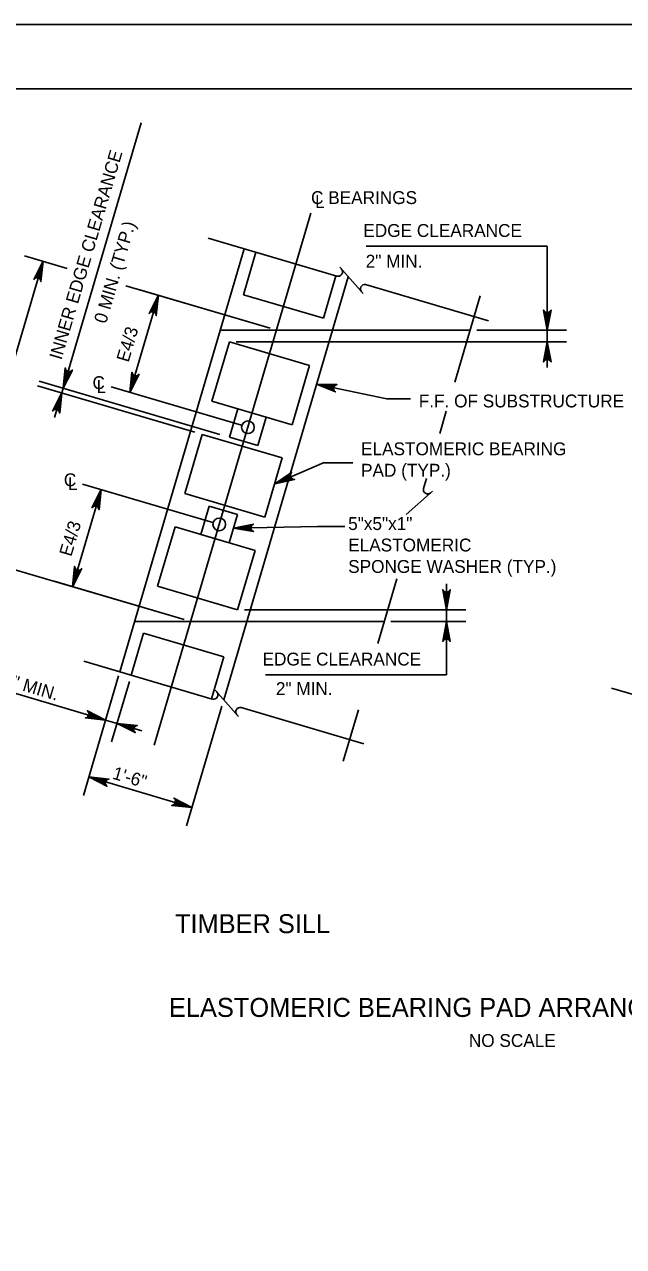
# Model space of a CAD drawing. Extents: x 638268 to 640277, y 295465 to 298435.
# Drawn here: x 639790.3 to 639930.1, y 298150.4 to 298435.5 of the extents above; entities that cross this region are included whole.
import ezdxf

# ---------------------------------------------------------------- set-up
doc = ezdxf.new("R2010")
doc.units = 0
for name, color, linetype in [('2', 7, 'Continuous'), ('3', 7, 'Continuous'), ('4', 7, 'Continuous'), ('7', 7, 'Continuous'), ('PLT-BNDY', 7, 'Continuous')]:
    doc.layers.add(name, color=color, linetype=linetype)

msp = doc.modelspace()

# ---------------------------------------------------------------- linework, layer by layer
at = {"layer": '2'}
msp.add_line((639316.46, 298420.46), (640102.46, 298420.46), dxfattribs=at)
at = {"layer": '3'}
for p, q in [((639833.22, 298385.58), (639863.23, 298376.74)), ((639812.58, 298284.45), (639841.64, 298383.1)), ((639774.66, 298312.22), (639794.68, 298380.2)), ((639800.32, 298378.54), (639790.36, 298381.47)), ((639863.93, 298378.81), (639869.34, 298372.67)), ((639847.64, 298364.6), (639814.01, 298374.5)), ((639865.89, 298376.59), (639836.83, 298277.94)), ((639869.94, 298374.77), (639898.62, 298366.32)), ((639841.42, 298372.42), (639860.11, 298366.91)), ((639896.68, 298372.12), (639890.74, 298351.98)), ((639836.06, 298364.16), (639894.33, 298364.16)), ((639838.17, 298361.4), (639856.86, 298355.9)), ((639835.93, 298339.83), (639793.74, 298352.26)), ((639830.12, 298340.34), (639793.42, 298351.16)), ((639834.09, 298347.56), (639852.79, 298342.05)), ((639840.14, 298345.77), (639846.74, 298343.83)), ((639888.77, 298345.26), (639887.23, 298340.03)), ((639831.82, 298339.84), (639850.51, 298334.34)), ((639838.19, 298339.17), (639844.8, 298337.22)), ((639884.13, 298329.51), (639883.46, 298327.24)), ((639827.74, 298326), (639846.44, 298320.49)), ((639885.52, 298326.55), (639879.39, 298321.13)), ((639833.46, 298323.12), (639840.07, 298321.17)), ((639825.47, 298318.29), (639844.17, 298312.78)), ((639831.51, 298316.51), (639838.12, 298314.56)), ((639827.62, 298296.62), (639770.34, 298313.49)), ((639877.23, 298306.11), (639872.8, 298291.07)), ((639821.39, 298304.44), (639840.09, 298298.93)), ((639816.04, 298296.18), (639874.31, 298296.18)), ((639818.15, 298293.42), (639836.84, 298287.92)), ((639804.17, 298286.93), (639834.18, 298278.09)), ((639834.87, 298280.16), (639840.28, 298274.02)), ((639840.89, 298276.12), (639869.56, 298267.67)), ((639868.25, 298275.6), (639864.71, 298263.61))]:
    msp.add_line(p, q, dxfattribs=at)
msp.add_lwpolyline([(639793.35, 298377.46), (639794.31, 298377.18), (639794.68, 298380.2)], close=True, dxfattribs=at)
for centre, start, end in [((639863.52, 298377.72), 253.588, 43.588), ((639869.75, 298373.76), 78.9166, 221.4552), ((639884.44, 298326.95), 163.588, 313.588), ((639834.47, 298279.08), 253.588, 43.588), ((639840.69, 298275.11), 78.9166, 221.4552)]:
    msp.add_arc(centre, 1.02, start, end, dxfattribs=at)
at = {"layer": '4'}
for p, q in [((639800.22, 298353.48), (639817.59, 298412.47)), ((639820.63, 298267.37), (639857.18, 298391.45)), ((639870.07, 298383.7), (639912.34, 298383.7)), ((639912.34, 298367.16), (639912.34, 298383.7)), ((639814.91, 298349.61), (639821.59, 298372.27)), ((639847.64, 298364.6), (639817.27, 298373.54)), ((639895.89, 298364.16), (639916.84, 298364.16)), ((639912.34, 298361.4), (639912.34, 298364.16)), ((639839.73, 298361.4), (639916.84, 298361.4)), ((639912.34, 298358.4), (639912.34, 298355.4)), ((639799.04, 298349.5), (639799.37, 298350.6)), ((639840.97, 298341.94), (639810.6, 298350.89)), ((639798.2, 298346.62), (639797.35, 298343.74)), ((639874.89, 298348.09), (639880.42, 298348.09)), ((639860.08, 298333.18), (639866.93, 298333.18)), ((639801.56, 298304.3), (639808.24, 298326.95)), ((639834.29, 298319.28), (639803.92, 298328.22)), ((639858.72, 298318.32), (639865.09, 298318.32)), ((639827.62, 298296.62), (639797.25, 298305.57)), ((639888.81, 298301.93), (639888.81, 298304.93)), ((639841.65, 298298.93), (639893.31, 298298.93)), ((639888.81, 298298.93), (639888.81, 298296.18)), ((639875.87, 298296.18), (639893.31, 298296.18)), ((639888.81, 298293.18), (639888.81, 298283.71)), ((639812.31, 298283.53), (639804.08, 298255.59)), ((639812.14, 298282.96), (639808, 298268.88)), ((639846.55, 298283.71), (639888.81, 298283.71)), ((639809.27, 298273.2), (639782.13, 298281.19)), ((639814.83, 298282.16), (639810.69, 298268.09)), ((639952.69, 298273.2), (639927.34, 298280.66)), ((639836.39, 298276.44), (639828.16, 298248.5)), ((639811.96, 298272.4), (639809.27, 298273.2)), ((639811.96, 298272.4), (639817.71, 298270.71)), ((639829.43, 298252.81), (639805.35, 298259.91))]:
    msp.add_line(p, q, dxfattribs=at)
for points in [[(639794.68, 298380.2), (639794.2, 298375.48), (639794.06, 298375.9), (639793.82, 298376.16), (639793.53, 298376.3), (639793.22, 298376.34), (639792.86, 298376.25), (639792.53, 298375.98), (639794.68, 298380.2), (639792.86, 298376.25), (639793.22, 298376.34), (639794.68, 298380.2), (639793.53, 298376.3), (639793.82, 298376.16), (639794.68, 298380.2), (639794.06, 298375.9)], [(639821.59, 298372.27), (639821.11, 298367.56), (639820.97, 298367.97), (639820.73, 298368.24), (639820.44, 298368.37), (639820.13, 298368.41), (639819.77, 298368.32), (639819.43, 298368.05), (639821.59, 298372.27), (639819.77, 298368.32), (639820.13, 298368.41), (639821.59, 298372.27), (639820.44, 298368.37), (639820.73, 298368.24), (639821.59, 298372.27), (639820.97, 298367.97)], [(639912.34, 298364.16), (639911.46, 298368.82), (639911.71, 298368.46), (639912.02, 298368.27), (639912.34, 298368.22), (639912.65, 298368.27), (639912.96, 298368.46), (639913.21, 298368.82), (639912.34, 298364.16), (639912.96, 298368.46), (639912.65, 298368.27), (639912.34, 298364.16), (639912.34, 298368.22), (639912.02, 298368.27), (639912.34, 298364.16), (639911.71, 298368.46)], [(639912.34, 298361.4), (639913.21, 298356.74), (639912.96, 298357.1), (639912.65, 298357.29), (639912.34, 298357.34), (639912.02, 298357.29), (639911.71, 298357.1), (639911.46, 298356.74), (639912.34, 298361.4), (639911.71, 298357.1), (639912.02, 298357.29), (639912.34, 298361.4), (639912.34, 298357.34), (639912.65, 298357.29), (639912.34, 298361.4), (639912.96, 298357.1)], [(639799.37, 298350.6), (639799.85, 298355.32), (639799.99, 298354.9), (639800.23, 298354.64), (639800.52, 298354.5), (639800.83, 298354.46), (639801.18, 298354.55), (639801.53, 298354.82), (639799.37, 298350.6), (639801.18, 298354.55), (639800.83, 298354.46), (639799.37, 298350.6), (639800.52, 298354.5), (639800.23, 298354.64), (639799.37, 298350.6), (639799.99, 298354.9)], [(639814.91, 298349.61), (639815.39, 298354.33), (639815.53, 298353.92), (639815.78, 298353.65), (639816.06, 298353.51), (639816.38, 298353.47), (639816.73, 298353.56), (639817.07, 298353.84), (639814.91, 298349.61), (639816.73, 298353.56), (639816.38, 298353.47), (639814.91, 298349.61), (639816.06, 298353.51), (639815.78, 298353.65), (639814.91, 298349.61), (639815.53, 298353.92)], [(639858.51, 298351.54), (639874.89, 298348.09)], [(639858.51, 298351.54), (639863.25, 298351.44), (639862.84, 298351.27), (639862.6, 298351), (639862.48, 298350.7), (639862.47, 298350.39), (639862.59, 298350.04), (639862.89, 298349.73), (639858.51, 298351.54), (639862.59, 298350.04), (639862.47, 298350.39), (639858.51, 298351.54), (639862.48, 298350.7), (639862.6, 298351), (639858.51, 298351.54), (639862.84, 298351.27)], [(639799.04, 298349.5), (639798.56, 298344.78), (639798.43, 298345.2), (639798.18, 298345.46), (639797.9, 298345.6), (639797.58, 298345.64), (639797.23, 298345.55), (639796.89, 298345.27), (639799.04, 298349.5), (639797.23, 298345.55), (639797.58, 298345.64), (639799.04, 298349.5), (639797.9, 298345.6), (639798.18, 298345.46), (639799.04, 298349.5), (639798.43, 298345.2)], [(639848.73, 298328.28), (639860.24, 298333.25)], [(639848.73, 298328.28), (639852.67, 298330.93), (639852.44, 298330.56), (639852.39, 298330.2), (639852.46, 298329.9), (639852.64, 298329.63), (639852.93, 298329.42), (639853.36, 298329.33), (639848.73, 298328.28), (639852.93, 298329.42), (639852.64, 298329.63), (639848.73, 298328.28), (639852.46, 298329.9), (639852.39, 298330.2), (639848.73, 298328.28), (639852.44, 298330.56)], [(639808.24, 298326.95), (639807.76, 298322.24), (639807.62, 298322.65), (639807.38, 298322.92), (639807.09, 298323.06), (639806.78, 298323.09), (639806.43, 298323), (639806.09, 298322.73), (639808.24, 298326.95), (639806.43, 298323), (639806.78, 298323.09), (639808.24, 298326.95), (639807.09, 298323.06), (639807.38, 298322.92), (639808.24, 298326.95), (639807.62, 298322.65)], [(639839.11, 298317.92), (639843.75, 298318.89), (639843.4, 298318.63), (639843.22, 298318.32), (639843.18, 298318), (639843.23, 298317.69), (639843.43, 298317.38), (639843.79, 298317.14), (639839.11, 298317.92), (639843.43, 298317.38), (639843.23, 298317.69), (639839.11, 298317.92), (639843.18, 298318), (639843.22, 298318.32), (639839.11, 298317.92), (639843.4, 298318.63)], [(639839.11, 298317.92), (639858.72, 298318.32)], [(639801.56, 298304.3), (639802.04, 298309.01), (639802.18, 298308.6), (639802.43, 298308.33), (639802.71, 298308.19), (639803.03, 298308.16), (639803.38, 298308.25), (639803.72, 298308.52), (639801.56, 298304.3), (639803.38, 298308.25), (639803.03, 298308.16), (639801.56, 298304.3), (639802.71, 298308.19), (639802.43, 298308.33), (639801.56, 298304.3), (639802.18, 298308.6)], [(639888.81, 298298.93), (639887.94, 298303.6), (639888.19, 298303.24), (639888.5, 298303.05), (639888.81, 298303), (639889.13, 298303.05), (639889.44, 298303.24), (639889.69, 298303.6), (639888.81, 298298.93), (639889.44, 298303.24), (639889.13, 298303.05), (639888.81, 298298.93), (639888.81, 298303), (639888.5, 298303.05), (639888.81, 298298.93), (639888.19, 298303.24)], [(639888.81, 298296.18), (639889.69, 298291.52), (639889.44, 298291.88), (639889.13, 298292.06), (639888.81, 298292.12), (639888.5, 298292.06), (639888.19, 298291.88), (639887.94, 298291.52), (639888.81, 298296.18), (639888.19, 298291.88), (639888.5, 298292.06), (639888.81, 298296.18), (639888.81, 298292.12), (639889.13, 298292.06), (639888.81, 298296.18), (639889.44, 298291.88)], [(639809.27, 298273.2), (639804.55, 298273.67), (639804.96, 298273.81), (639805.23, 298274.06), (639805.37, 298274.34), (639805.41, 298274.66), (639805.32, 298275.01), (639805.04, 298275.35), (639809.27, 298273.2), (639805.32, 298275.01), (639805.41, 298274.66), (639809.27, 298273.2), (639805.37, 298274.34), (639805.23, 298274.06), (639809.27, 298273.2), (639804.96, 298273.81)], [(639811.96, 298272.4), (639816.67, 298271.92), (639816.26, 298271.79), (639815.99, 298271.54), (639815.85, 298271.26), (639815.82, 298270.94), (639815.91, 298270.59), (639816.18, 298270.25), (639811.96, 298272.4), (639815.91, 298270.59), (639815.82, 298270.94), (639811.96, 298272.4), (639815.85, 298271.26), (639815.99, 298271.54), (639811.96, 298272.4), (639816.26, 298271.79)], [(639805.35, 298259.91), (639810.07, 298259.43), (639809.65, 298259.29), (639809.39, 298259.04), (639809.25, 298258.76), (639809.21, 298258.44), (639809.3, 298258.09), (639809.58, 298257.75), (639805.35, 298259.91), (639809.3, 298258.09), (639809.21, 298258.44), (639805.35, 298259.91), (639809.25, 298258.76), (639809.39, 298259.04), (639805.35, 298259.91), (639809.65, 298259.29)], [(639829.43, 298252.81), (639824.71, 298253.29), (639825.13, 298253.43), (639825.39, 298253.68), (639825.53, 298253.96), (639825.57, 298254.28), (639825.48, 298254.63), (639825.2, 298254.97), (639829.43, 298252.81), (639825.48, 298254.63), (639825.57, 298254.28), (639829.43, 298252.81), (639825.53, 298253.96), (639825.39, 298253.68), (639829.43, 298252.81), (639825.13, 298253.43)]]:
    msp.add_lwpolyline(points, dxfattribs=at)
for points in [[(639820.26, 298369.54), (639821.22, 298369.25), (639821.59, 298372.27)], [(639911.84, 298367.16), (639912.84, 298367.16), (639912.34, 298364.16)], [(639911.84, 298358.4), (639912.84, 298358.4), (639912.34, 298361.4)], [(639799.74, 298353.62), (639800.7, 298353.34), (639799.37, 298350.6)], [(639815.28, 298352.63), (639816.24, 298352.35), (639814.91, 298349.61)], [(639858.51, 298351.54), (639861.39, 298350.68), (639861.49, 298351.17)], [(639797.72, 298346.76), (639798.68, 298346.48), (639799.04, 298349.5)], [(639848.73, 298328.28), (639851.59, 298329.24), (639851.39, 298329.7)], [(639806.91, 298324.22), (639807.87, 298323.93), (639808.24, 298326.95)], [(639801.93, 298307.31), (639802.89, 298307.03), (639801.56, 298304.29)], [(639888.31, 298301.93), (639889.31, 298301.93), (639888.81, 298298.93)], [(639888.31, 298293.18), (639889.31, 298293.18), (639888.81, 298296.18)], [(639806.53, 298274.52), (639806.25, 298273.56), (639809.27, 298273.2)], [(639814.98, 298272.04), (639814.69, 298271.08), (639811.96, 298272.4)], [(639808.37, 298259.54), (639808.09, 298258.58), (639805.35, 298259.91)], [(639826.69, 298254.14), (639826.41, 298253.18), (639829.43, 298252.81)]]:
    msp.add_lwpolyline(points, close=True, dxfattribs=at)
at = {"layer": '7'}
for p, q in [((639841.42, 298372.42), (639844.33, 298382.31)), ((639860.11, 298366.91), (639863.02, 298376.8)), ((639834.09, 298347.56), (639838.17, 298361.4)), ((639852.79, 298342.05), (639856.86, 298355.9)), ((639838.19, 298339.17), (639840.14, 298345.77)), ((639844.8, 298337.22), (639846.74, 298343.83)), ((639827.74, 298326), (639831.82, 298339.84)), ((639846.44, 298320.49), (639850.51, 298334.34)), ((639831.51, 298316.51), (639833.46, 298323.12)), ((639838.12, 298314.56), (639840.07, 298321.17)), ((639821.39, 298304.44), (639825.47, 298318.29)), ((639840.09, 298298.93), (639844.17, 298312.78)), ((639815.27, 298283.66), (639818.15, 298293.42)), ((639833.97, 298278.16), (639836.84, 298287.92))]:
    msp.add_line(p, q, dxfattribs=at)
for centre in [(639842.47, 298341.5), (639835.79, 298318.84)]:
    msp.add_circle(centre, 1.48, dxfattribs=at)
at = {"layer": 'PLT-BNDY'}
msp.add_lwpolyline([(639276.46, 298435.46), (640117.46, 298435.46), (640117.46, 297841.46), (639276.46, 297841.46)], close=True, dxfattribs=at)

# ---------------------------------------------------------------- texts
at = {"layer": '3'}
for s, p in [('TIMBER SILL', (639825.46, 298223.48)), ('ELASTOMERIC BEARING PAD ARRANGEMENTS', (639824.06, 298203.94))]:
    msp.add_text(s, height=4.4292, dxfattribs=at).set_placement(p)
at = {"layer": '4'}
for s, rotation, p in [('INNER EDGE CLEARANCE', 73.588, (639798.95, 298357.05)), ('0 MIN. (TYP.)', 73.588, (639809.38, 298365.51)), ('E4/3', 73.588, (639814.62, 298356.49)), ('E4/3', 73.588, (639801.27, 298311.17)), ('2" MIN.', 343.588, (639785.12, 298281.43)), ('1\'-6"', 343.588, (639810.68, 298259.54))]:
    msp.add_text(s, height=3, rotation=rotation, dxfattribs=at).set_placement(p)
for s, p in [('C BEARINGS', (639857.21, 298393.56)), ('L', (639858.16, 298392.65)), ('EDGE CLEARANCE', (639869.42, 298385.89)), ('2" MIN.', (639869.97, 298378.73)), ('C', (639806.21, 298350.39)), ('L', (639807.15, 298349.48)), ('F.F. OF SUBSTRUCTURE', (639882.35, 298346.12)), ('ELASTOMERIC BEARING', (639868.88, 298334.96)), ('PAD (TYP.)', (639868.88, 298329.96)), ('C', (639799.53, 298327.73)), ('L', (639800.48, 298326.82)), ('5"x5"x1"', (639865.88, 298317.52)), ('ELASTOMERIC', (639865.88, 298312.52)), ('SPONGE WASHER (TYP.)', (639865.88, 298307.52)), ('EDGE CLEARANCE', (639845.9, 298285.91)), ('2" MIN.', (639849.01, 298279.03)), ('NO SCALE', (639894.04, 298196.94))]:
    msp.add_text(s, height=3, dxfattribs=at).set_placement(p)

doc.saveas('drawing.dxf')
